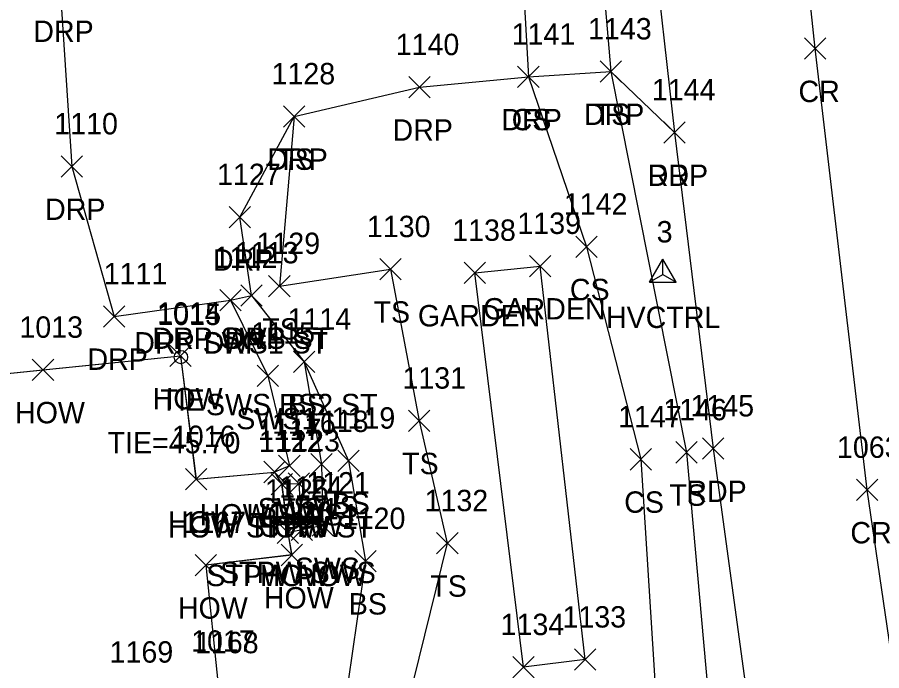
# Model space of a CAD drawing. Extents: x 1512665 to 1513714, y 110636 to 112816.
# Drawn here: x 1513126.6 to 1513207.4, y 111019.1 to 111080.2 of the extents above; entities that cross this region are included whole.
import ezdxf

# ---------------------------------------------------------------- set-up
doc = ezdxf.new("R2010")
doc.units = 0
for name, color, linetype in [('C_A', 7, 'Continuous'), ('C_C', 7, 'Continuous'), ('C_I', 7, 'Continuous'), ('CBP', 7, 'Continuous'), ('CPSM', 7, 'Continuous'), ('L_A', 7, 'Continuous'), ('L_I', 7, 'Continuous'), ('L_TIC', 7, 'Continuous'), ('LAPB', 7, 'Continuous'), ('LBC', 7, 'Continuous'), ('LBF', 7, 'Continuous'), ('LELB', 7, 'Continuous'), ('Level 13', 7, 'Continuous'), ('P_A', 7, 'Continuous'), ('P_I', 7, 'Continuous'), ('P_TIC', 7, 'Continuous'), ('PET', 7, 'Continuous'), ('PRC', 7, 'Continuous'), ('R_A', 7, 'Continuous'), ('R_I', 7, 'Continuous'), ('R_TIC', 7, 'Continuous'), ('RDP', 7, 'Continuous'), ('RSW', 7, 'Continuous')]:
    doc.layers.add(name, color=color, linetype=linetype)

msp = doc.modelspace()

# ---------------------------------------------------------------- linework, layer by layer
at = {"layer": 'CBP'}
for radius in [0.625, 0.0833]:
    msp.add_circle((1513141.873, 111048.399), radius, dxfattribs=at)
at = {"layer": 'CPSM'}
for p, q in [((1513185.669, 111055.404), (1513186.919, 111057.569)), ((1513185.669, 111055.404), (1513186.919, 111057.569)), ((1513185.669, 111055.404), (1513186.919, 111057.569)), ((1513185.669, 111055.404), (1513186.919, 111057.569)), ((1513188.169, 111055.404), (1513186.919, 111057.569)), ((1513186.919, 111056.125), (1513186.919, 111057.569)), ((1513188.169, 111055.404), (1513186.919, 111057.569)), ((1513186.919, 111056.125), (1513186.919, 111057.569)), ((1513188.169, 111055.404), (1513186.919, 111057.569)), ((1513186.919, 111056.125), (1513186.919, 111057.569)), ((1513188.169, 111055.404), (1513186.919, 111057.569)), ((1513186.919, 111056.125), (1513186.919, 111057.569)), ((1513185.669, 111055.404), (1513186.919, 111056.125)), ((1513185.669, 111055.404), (1513186.919, 111056.125)), ((1513185.669, 111055.404), (1513186.919, 111056.125)), ((1513185.669, 111055.404), (1513186.919, 111056.125)), ((1513186.919, 111056.125), (1513186.919, 111056.125)), ((1513186.919, 111056.125), (1513188.169, 111055.404)), ((1513186.919, 111056.125), (1513186.919, 111056.125)), ((1513186.919, 111056.125), (1513188.169, 111055.404)), ((1513186.919, 111056.125), (1513186.919, 111056.125)), ((1513186.919, 111056.125), (1513188.169, 111055.404)), ((1513186.919, 111056.125), (1513186.919, 111056.125)), ((1513186.919, 111056.125), (1513188.169, 111055.404)), ((1513185.669, 111055.404), (1513188.169, 111055.404)), ((1513185.669, 111055.404), (1513188.169, 111055.404)), ((1513185.669, 111055.404), (1513188.169, 111055.404)), ((1513185.669, 111055.404), (1513188.169, 111055.404))]:
    msp.add_line(p, q, dxfattribs=at)
at = {"layer": 'L_TIC'}
for points in [[(1513181.065, 111074.11), (1513183.065, 111076.11)], [(1513183.065, 111074.11), (1513181.065, 111076.11)], [(1513173.355, 111073.616), (1513175.355, 111075.616)], [(1513175.355, 111073.616), (1513173.355, 111075.616)], [(1513151.471, 111069.911), (1513153.471, 111071.911)], [(1513153.471, 111069.911), (1513151.471, 111071.911)], [(1513178.798, 111057.724), (1513180.798, 111059.724)], [(1513180.798, 111057.724), (1513178.798, 111059.724)], [(1513160.472, 111055.619), (1513162.472, 111057.619)], [(1513162.472, 111055.619), (1513160.472, 111057.619)], [(1513174.465, 111055.919), (1513176.465, 111057.919)], [(1513176.465, 111055.919), (1513174.465, 111057.919)], [(1513174.465, 111055.919), (1513176.465, 111057.919)], [(1513176.465, 111055.919), (1513174.465, 111057.919)], [(1513168.362, 111055.274), (1513170.362, 111057.274)], [(1513170.362, 111055.274), (1513168.362, 111057.274)], [(1513150.073, 111054.043), (1513152.073, 111056.043)], [(1513152.073, 111054.043), (1513150.073, 111056.043)], [(1513140.844, 111047.525), (1513142.844, 111049.525)], [(1513142.844, 111047.525), (1513140.844, 111049.525)], [(1513152.398, 111046.966), (1513154.398, 111048.966)], [(1513154.398, 111046.966), (1513152.398, 111048.966)], [(1513127.974, 111046.21), (1513129.974, 111048.21)], [(1513129.974, 111046.21), (1513127.974, 111048.21)], [(1513163.142, 111041.453), (1513165.142, 111043.453)], [(1513165.142, 111041.453), (1513163.142, 111043.453)], [(1513156.531, 111037.71), (1513158.531, 111039.71)], [(1513158.531, 111037.71), (1513156.531, 111039.71)], [(1513183.877, 111037.844), (1513185.877, 111039.844)], [(1513185.877, 111037.844), (1513183.877, 111039.844)], [(1513188.147, 111038.495), (1513190.147, 111040.495)], [(1513190.147, 111038.495), (1513188.147, 111040.495)], [(1513149.612, 111036.656), (1513151.612, 111038.656)], [(1513151.612, 111036.656), (1513149.612, 111038.656)], [(1513142.285, 111035.994), (1513144.285, 111037.994)], [(1513144.285, 111035.994), (1513142.285, 111037.994)], [(1513150.294, 111035.531), (1513152.294, 111037.531)], [(1513152.294, 111035.531), (1513150.294, 111037.531)], [(1513150.294, 111035.531), (1513152.294, 111037.531)], [(1513152.294, 111035.531), (1513150.294, 111037.531)], [(1513151.909, 111035.581), (1513153.909, 111037.581)], [(1513153.909, 111035.581), (1513151.909, 111037.581)], [(1513152.173, 111031.264), (1513154.173, 111033.264)], [(1513154.173, 111031.264), (1513152.173, 111033.264)], [(1513150.864, 111030.982), (1513152.864, 111032.982)], [(1513152.864, 111030.982), (1513150.864, 111032.982)], [(1513150.864, 111030.982), (1513152.864, 111032.982)], [(1513152.864, 111030.982), (1513150.864, 111032.982)], [(1513165.779, 111029.992), (1513167.779, 111031.992)], [(1513167.779, 111029.992), (1513165.779, 111031.992)], [(1513151.237, 111028.894), (1513153.237, 111030.894)], [(1513153.237, 111028.894), (1513151.237, 111030.894)], [(1513158.125, 111028.326), (1513160.125, 111030.326)], [(1513160.125, 111028.326), (1513158.125, 111030.326)], [(1513143.204, 111027.943), (1513145.204, 111029.943)], [(1513145.204, 111027.943), (1513143.204, 111029.943)], [(1513178.672, 111019.11), (1513180.672, 111021.11)], [(1513180.672, 111019.11), (1513178.672, 111021.11)], [(1513178.672, 111019.11), (1513180.672, 111021.11)], [(1513180.672, 111019.11), (1513178.672, 111021.11)], [(1513172.89, 111018.403), (1513174.89, 111020.403)], [(1513174.89, 111018.403), (1513172.89, 111020.403)]]:
    msp.add_lwpolyline(points, dxfattribs=at)
at = {"layer": 'LAPB'}
for points in [[(1513179.672, 111020.11), (1513173.89, 111019.403), (1513169.362, 111056.274), (1513175.465, 111056.919)], [(1513179.672, 111020.11), (1513175.465, 111056.919)]]:
    msp.add_lwpolyline(points, dxfattribs=at)
at = {"layer": 'LBC'}
msp.add_lwpolyline([(1513118.388, 111046.131), (1513128.974, 111047.21), (1513141.844, 111048.525), (1513143.285, 111036.994), (1513150.612, 111037.656), (1513151.294, 111036.531), (1513151.864, 111031.982), (1513152.237, 111029.894), (1513144.204, 111028.943), (1513145.361, 111017.708), (1513137.385, 111016.829), (1513138.645, 111001.096), (1513139.172, 110995.766), (1513139.383, 110992.132), (1513138.775, 110991.845), (1513123.648, 110990.593), (1513123.337, 110990.753), (1513123.275, 110992.806), (1513122.614, 111004.463), (1513120.694, 111023.787), (1513118.555, 111043.769)], dxfattribs=at)
at = {"layer": 'LBF'}
msp.add_lwpolyline([(1513151.294, 111036.531), (1513152.909, 111036.581), (1513153.173, 111032.264), (1513151.864, 111031.982)], dxfattribs=at)
at = {"layer": 'LELB'}
for points in [[(1513177.696, 111131.29), (1513178.538, 111113.909), (1513180.617, 111092.198), (1513182.065, 111075.11), (1513189.147, 111039.495), (1513191.756, 111010.28), (1513193.885, 111000.55), (1513190.646, 110994.729)], [(1513170.214, 111130.816), (1513170.8, 111112.207), (1513173.531, 111089.539), (1513174.355, 111074.616), (1513179.798, 111058.724), (1513184.877, 111038.844), (1513186.524, 111012.71), (1513182.7, 110990.922), (1513167.492, 110986.513), (1513158.395, 110982.164)], [(1513152.471, 111070.911), (1513151.073, 111055.043), (1513161.472, 111056.619), (1513164.142, 111042.453), (1513166.779, 111030.992), (1513161.988, 111011.639), (1513161.319, 110997.122), (1513158.395, 110982.164)], [(1513153.398, 111047.966), (1513157.531, 111038.71), (1513159.125, 111029.326), (1513156.691, 111012.489), (1513154.494, 111000.03)]]:
    msp.add_lwpolyline(points, dxfattribs=at)
at = {"layer": 'Level 13'}
msp.add_lwpolyline([(1513123.644, 110990.606), (1513123.347, 110990.764), (1513123.285, 110992.81), (1513122.624, 111004.459), (1513120.705, 111023.788), (1513118.567, 111043.766), (1513118.402, 111046.123), (1513128.978, 111047.2), (1513141.835, 111048.514), (1513143.273, 111036.981), (1513150.611, 111037.648), (1513151.284, 111036.528), (1513151.853, 111031.979), (1513152.224, 111029.902), (1513144.191, 111028.956), (1513145.349, 111017.72), (1513137.373, 111016.842), (1513138.634, 111001.097), (1513139.163, 110995.765), (1513139.374, 110992.138), (1513138.775, 110991.854)], close=True, dxfattribs=at)
at = {"layer": 'P_TIC'}
for points in [[(1513200.182, 111076.251), (1513202.182, 111078.251)], [(1513202.182, 111076.251), (1513200.182, 111078.251)], [(1513187.028, 111068.406), (1513189.028, 111070.406)], [(1513189.028, 111068.406), (1513187.028, 111070.406)], [(1513190.639, 111038.849), (1513192.639, 111040.849)], [(1513192.639, 111038.849), (1513190.639, 111040.849)], [(1513205.033, 111034.98), (1513207.033, 111036.98)], [(1513207.033, 111034.98), (1513205.033, 111036.98)]]:
    msp.add_lwpolyline(points, dxfattribs=at)
at = {"layer": 'PET'}
msp.add_lwpolyline([(1513181.776, 111131.319), (1513183.338, 111114.054), (1513184.43, 111101.236), (1513188.028, 111069.406), (1513191.639, 111039.849), (1513195.641, 111010.584), (1513196.783, 111002.78), (1513199.52, 110982.675), (1513202.263, 110966.835), (1513206.801, 110942.098), (1513212.833, 110910.789), (1513216.968, 110890.917), (1513223.708, 110861.112), (1513236.039, 110809.069), (1513241.458, 110788.527), (1513249.294, 110760.242)], dxfattribs=at)
at = {"layer": 'PRC'}
msp.add_lwpolyline([(1513262.692, 110765.317), (1513252.951, 110800.58), (1513242.765, 110841.606), (1513231.954, 110888.448), (1513222.372, 110936.123), (1513216.373, 110968.756), (1513211.795, 110996.68), (1513206.033, 111035.98), (1513201.182, 111077.251), (1513198.65, 111101.069), (1513195.743, 111132.859)], dxfattribs=at)
at = {"layer": 'R_TIC'}
for points in [[(1513181.065, 111074.11), (1513183.065, 111076.11)], [(1513183.065, 111074.11), (1513181.065, 111076.11)], [(1513173.355, 111073.616), (1513175.355, 111075.616)], [(1513175.355, 111073.616), (1513173.355, 111075.616)], [(1513163.166, 111072.64), (1513165.166, 111074.64)], [(1513165.166, 111072.64), (1513163.166, 111074.64)], [(1513151.471, 111069.911), (1513153.471, 111071.911)], [(1513153.471, 111069.911), (1513151.471, 111071.911)], [(1513187.028, 111068.406), (1513189.028, 111070.406)], [(1513189.028, 111068.406), (1513187.028, 111070.406)], [(1513130.678, 111065.231), (1513132.678, 111067.231)], [(1513132.678, 111065.231), (1513130.678, 111067.231)], [(1513146.377, 111060.486), (1513148.377, 111062.486)], [(1513148.377, 111060.486), (1513146.377, 111062.486)], [(1513147.477, 111053.17), (1513149.477, 111055.17)], [(1513149.477, 111053.17), (1513147.477, 111055.17)], [(1513147.477, 111053.17), (1513149.477, 111055.17)], [(1513149.477, 111053.17), (1513147.477, 111055.17)], [(1513145.507, 111052.737), (1513147.507, 111054.737)], [(1513147.507, 111052.737), (1513145.507, 111054.737)], [(1513145.507, 111052.737), (1513147.507, 111054.737)], [(1513147.507, 111052.737), (1513145.507, 111054.737)], [(1513134.641, 111051.21), (1513136.641, 111053.21)], [(1513136.641, 111051.21), (1513134.641, 111053.21)], [(1513152.398, 111046.966), (1513154.398, 111048.966)], [(1513154.398, 111046.966), (1513152.398, 111048.966)], [(1513149.006, 111045.657), (1513151.006, 111047.657)], [(1513151.006, 111045.657), (1513149.006, 111047.657)], [(1513151.008, 111037.227), (1513153.008, 111039.227)], [(1513153.008, 111037.227), (1513151.008, 111039.227)], [(1513154.025, 111037.398), (1513156.025, 111039.398)], [(1513156.025, 111037.398), (1513154.025, 111039.398)], [(1513149.612, 111036.656), (1513151.612, 111038.656)], [(1513151.612, 111036.656), (1513149.612, 111038.656)], [(1513152.173, 111031.264), (1513154.173, 111033.264)], [(1513154.173, 111031.264), (1513152.173, 111033.264)], [(1513154.148, 111031.646), (1513156.148, 111033.646)], [(1513156.148, 111031.646), (1513154.148, 111033.646)]]:
    msp.add_lwpolyline(points, dxfattribs=at)
at = {"layer": 'RDP'}
msp.add_lwpolyline([(1513184.43, 111101.236), (1513180.617, 111092.198), (1513173.531, 111089.539), (1513165.119, 111088.624), (1513150.623, 111086.619), (1513130.582, 111082.877), (1513131.678, 111066.231), (1513135.641, 111052.21), (1513146.507, 111053.737), (1513148.477, 111054.17), (1513147.377, 111061.486), (1513152.471, 111070.911), (1513164.166, 111073.64), (1513174.355, 111074.616), (1513182.065, 111075.11), (1513188.028, 111069.406)], dxfattribs=at)
at = {"layer": 'RSW'}
for points in [[(1513146.507, 111053.737), (1513150.006, 111046.657), (1513152.008, 111038.227), (1513150.612, 111037.656)], [(1513148.477, 111054.17), (1513153.398, 111047.966), (1513155.025, 111038.398), (1513155.148, 111032.646), (1513153.173, 111032.264)]]:
    msp.add_lwpolyline(points, dxfattribs=at)

# ---------------------------------------------------------------- texts
at = {"layer": 'C_A'}
for s, p in [('HVCTRL', (1513181.612, 111051.125)), ('HVCTRL', (1513181.612, 111051.125)), ('HVCTRL', (1513181.612, 111051.125)), ('HVCTRL', (1513181.612, 111051.125)), ('TIE', (1513139.952, 111043.399))]:
    msp.add_text(s, height=2, dxfattribs=at).set_placement(p)
at = {"layer": 'C_C'}
msp.add_text('TIE=45.70', height=2, dxfattribs=at).set_placement((1513135.015, 111039.399))
at = {"layer": 'C_I'}
for s, p in [('3', (1513186.352, 111059.125)), ('3', (1513186.352, 111059.125)), ('3', (1513186.352, 111059.125)), ('3', (1513186.352, 111059.125)), ('1015', (1513139.669, 111051.399)), ('1017', (1513142.826, 111020.845))]:
    msp.add_text(s, height=2, dxfattribs=at).set_placement(p)
at = {"layer": 'L_A'}
for s, p in [('TS', (1513180.475, 111070.11)), ('CS', (1513172.796, 111069.616)), ('TS', (1513150.88, 111065.911)), ('CS', (1513178.239, 111053.724)), ('TS', (1513159.881, 111051.619)), ('GARDEN', (1513170.134, 111051.919)), ('GARDEN', (1513170.134, 111051.919)), ('GARDEN', (1513164.031, 111051.274)), ('TS', (1513149.483, 111050.043)), ('HOW', (1513139.23, 111043.525)), ('BS', (1513151.839, 111042.966)), ('HOW', (1513126.36, 111042.21)), ('TS', (1513162.551, 111037.453)), ('TS', (1513187.556, 111034.495)), ('BS', (1513155.972, 111033.71)), ('CS', (1513183.318, 111033.844)), ('HOW', (1513147.998, 111032.656)), ('HOW', (1513140.671, 111031.994)), ('HOW STPW ST', (1513140.672, 111031.531)), ('HOW', (1513148.679, 111031.531)), ('STPW', (1513149.303, 111031.581)), ('STPW SWS', (1513145.535, 111027.264)), ('STPW HOW', (1513144.242, 111026.982)), ('HOW', (1513149.25, 111026.982)), ('TS', (1513165.189, 111025.992)), ('HOW', (1513149.623, 111024.894)), ('HOW', (1513141.589, 111023.943)), ('BS', (1513157.566, 111024.326))]:
    msp.add_text(s, height=2, dxfattribs=at).set_placement(p)
at = {"layer": 'L_I'}
for s, p in [('1143', (1513179.939, 111078.11)), ('1141', (1513172.796, 111077.616)), ('1128', (1513150.345, 111073.911)), ('1142', (1513177.672, 111061.724)), ('1130', (1513159.259, 111059.619)), ('1139', (1513173.331, 111059.919)), ('1139', (1513173.331, 111059.919)), ('1138', (1513167.236, 111059.274)), ('1129', (1513148.939, 111058.043)), ('1014', (1513139.639, 111051.525)), ('1114', (1513151.839, 111050.966)), ('1013', (1513126.769, 111050.21)), ('1131', (1513162.583, 111045.453)), ('1119', (1513155.964, 111041.71)), ('1147', (1513182.751, 111041.844)), ('1146', (1513186.966, 111042.495)), ('1117', (1513149.053, 111040.656)), ('1016', (1513141.025, 111039.994)), ('1122', (1513149.168, 111039.531)), ('1122', (1513149.168, 111039.531)), ('1123', (1513150.783, 111039.581)), ('1124', (1513151.047, 111035.264)), ('1125', (1513149.738, 111034.982)), ('1125', (1513149.738, 111034.982)), ('1132', (1513164.653, 111033.992)), ('1126', (1513150.056, 111032.894)), ('1120', (1513156.912, 111032.326)), ('1167', (1513142.03, 111031.943)), ('1134', (1513171.764, 111022.403)), ('1133', (1513177.546, 111023.11)), ('1133', (1513177.546, 111023.11)), ('1168', (1513143.188, 111020.708)), ('1169', (1513135.204, 111019.829))]:
    msp.add_text(s, height=2, dxfattribs=at).set_placement(p)
at = {"layer": 'P_A'}
for s, p in [('CR', (1513199.615, 111072.251)), ('RDP', (1513185.516, 111064.406)), ('RDP', (1513189.127, 111034.849)), ('CR', (1513204.466, 111030.98))]:
    msp.add_text(s, height=2, dxfattribs=at).set_placement(p)
at = {"layer": 'P_I'}
for s, p in [('1144', (1513185.902, 111072.406)), ('1145', (1513189.513, 111042.849)), ('1063', (1513203.214, 111038.98))]:
    msp.add_text(s, height=2, dxfattribs=at).set_placement(p)
at = {"layer": 'R_A'}
for s, p in [('DRP', (1513128.07, 111077.877)), ('DRP', (1513179.553, 111070.11)), ('DRP', (1513171.843, 111069.616)), ('DRP', (1513161.654, 111068.64)), ('DRP', (1513149.959, 111065.911)), ('DRP', (1513185.516, 111064.406)), ('DRP', (1513129.166, 111061.231)), ('DRP', (1513144.865, 111056.486)), ('DRP SWS ST', (1513139.193, 111049.17)), ('DRP', (1513145.965, 111049.17)), ('DRP SWS1 ST', (1513137.507, 111048.737)), ('DRP', (1513143.995, 111048.737)), ('DRP', (1513133.13, 111047.21)), ('SWS BS2 ST', (1513144.209, 111042.966)), ('SWS1', (1513147.046, 111041.657)), ('SWS1', (1513149.048, 111033.227)), ('SWS', (1513152.395, 111033.398)), ('HOW SWS1', (1513143.636, 111032.656)), ('STPW SWS', (1513145.535, 111027.264)), ('SWS', (1513152.518, 111027.646))]:
    msp.add_text(s, height=2, dxfattribs=at).set_placement(p)
at = {"layer": 'R_I'}
for s, p in [('1143', (1513179.939, 111078.11)), ('1141', (1513172.796, 111077.616)), ('1140', (1513161.953, 111076.64)), ('1128', (1513150.345, 111073.911)), ('1144', (1513185.902, 111072.406)), ('1110', (1513130.032, 111069.231)), ('1127', (1513145.251, 111064.486)), ('1113', (1513146.918, 111057.17)), ('1113', (1513146.918, 111057.17)), ('1112', (1513144.948, 111056.737)), ('1112', (1513144.948, 111056.737)), ('1111', (1513134.649, 111055.21)), ('1114', (1513151.839, 111050.966)), ('1115', (1513148.447, 111049.657)), ('1116', (1513150.394, 111041.227)), ('1118', (1513153.466, 111041.398)), ('1117', (1513149.053, 111040.656)), ('1124', (1513151.047, 111035.264)), ('1121', (1513153.589, 111035.646))]:
    msp.add_text(s, height=2, dxfattribs=at).set_placement(p)

doc.saveas('drawing.dxf')
